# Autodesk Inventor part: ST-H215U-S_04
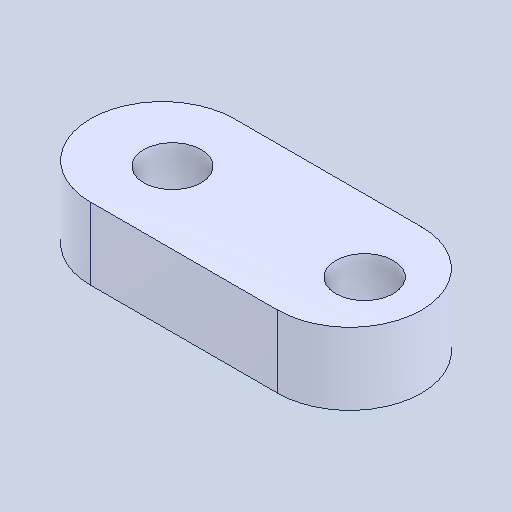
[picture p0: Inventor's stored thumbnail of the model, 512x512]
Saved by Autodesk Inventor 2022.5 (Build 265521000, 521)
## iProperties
Created: 2024-07
Part Number: ST-H215U-S_04
Material: 一般
Document SubType Name: Modeling
Designer: ImaoCorp
Density: 1 g/cm^3
Appearance: 既定
Author: ImaoCorp
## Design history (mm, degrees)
feature "ST-H215U-S_04"
node "ソリッド1"
